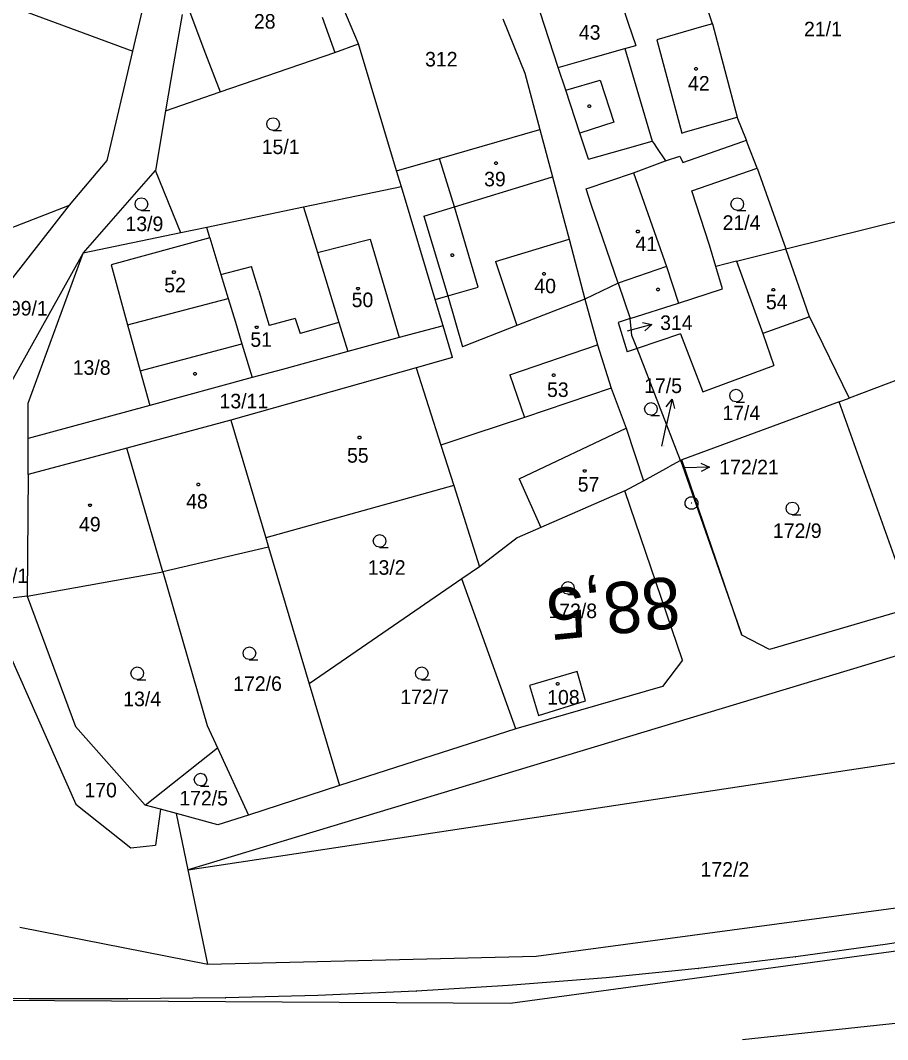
# Model space of a CAD drawing. Extents: x -780000 to -777378, y -1011169 to -1009297.
# Drawn here: x -779187.7 to -779086.3, y -1010479.3 to -1010360.1 of the extents above; entities that cross this region are included whole.
import ezdxf

# ---------------------------------------------------------------- set-up
doc = ezdxf.new("R2010")
doc.units = 0
for name, color, linetype in [('Default', 7, 'Continuous'), ('KN_HRANICE', 7, 'Continuous'), ('KN_KULTURY', 7, 'Continuous'), ('KN_PARCELY', 7, 'Continuous'), ('KN_SLUCKY', 7, 'Continuous'), ('KN_VEDENI', 7, 'Continuous'), ('Vrstva 7', 7, 'Continuous'), ('Železniční svršek', 7, 'Continuous')]:
    doc.layers.add(name, color=color, linetype=linetype)

# ---------------------------------------------------------------- blocks, each defined once
blk = doc.blocks.new('101')
at = {"layer": 'Default'}
blk.add_line((-0.05, 0), (0.05, 0), dxfattribs=at)
blk.add_lwpolyline([(0.19, 0.72), (0.53, 0.53), (0.72, 0.19), (0.72, -0.2), (0.53, -0.54), (0.19, -0.73), (-0.2, -0.73), (-0.54, -0.54), (-0.73, -0.2), (-0.73, 0.19), (-0.54, 0.53), (-0.2, 0.72), (0.19, 0.72)], dxfattribs=at)
blk = doc.blocks.new('304')
at = {"layer": 'Default'}
blk.add_lwpolyline([(0, 0), (-0.38, 0.1), (-0.65, 0.37), (-0.75, 0.74), (-0.65, 1.11), (-0.38, 1.38), (-0.01, 1.48), (0.36, 1.38), (0.63, 1.11), (0.73, 0.73), (0.63, 0.35), (0.36, 0.08), (-0.02, -0.02), (0.98, -0.02)], dxfattribs=at)
blk = doc.blocks.new('NAHRADNI_SYMBOL')
at = {"layer": 'Default'}
blk.add_lwpolyline([(0.09, 0.15), (0.18, 0), (0.09, -0.15), (-0.09, -0.15), (-0.18, 0), (-0.09, 0.15), (0.09, 0.15)], dxfattribs=at)
blk = doc.blocks.new('10292')
at = {"layer": 'Default'}
blk.add_line((0, 3), (0, 0), dxfattribs=at)
blk.add_lwpolyline([(-0.5, 2), (0, 3), (0.5, 2)], dxfattribs=at)
blk = doc.blocks.new('402')
at = {"layer": 'Default'}
blk.add_lwpolyline([(0.09, 0.15), (0.18, 0), (0.09, -0.15), (-0.09, -0.15), (-0.18, 0), (-0.09, 0.15), (0.09, 0.15)], dxfattribs=at)

msp = doc.modelspace()

# ---------------------------------------------------------------- linework, layer by layer
at = {"layer": 'KN_HRANICE'}
for p, q in [((-779174.51, -1010363.75), (-779172.96, -1010357.18)), ((-779106.8, -1010360.53), (-779107.71, -1010357.68)), ((-779187.61, -1010358.93), (-779174.51, -1010363.75)), ((-779148.14, -1010362.87), (-779149.85, -1010358.82)), ((-779124.81, -1010365.65), (-779126.93, -1010359.19)), ((-779117.35, -1010358.34), (-779116.64, -1010360.46)), ((-779168.77, -1010359.47), (-779169.76, -1010365.24)), ((-779131.3, -1010359.95), (-779128.72, -1010366.32)), ((-779116.64, -1010360.46), (-779115.76, -1010363.08)), ((-779106.8, -1010360.53), (-779103.91, -1010371.45)), ((-779150.92, -1010363.88), (-779148.14, -1010362.87)), ((-779143.7, -1010377.71), (-779148.14, -1010362.87)), ((-779177.51, -1010376.54), (-779174.51, -1010363.75)), ((-779164.31, -1010368.5), (-779150.92, -1010363.88)), ((-779117.03, -1010363.44), (-779115.76, -1010363.08)), ((-779117.03, -1010363.44), (-779113.83, -1010374.27)), ((-779169.76, -1010365.24), (-779170.69, -1010370.7)), ((-779128.72, -1010366.32), (-779126.96, -1010372.9)), ((-779123.93, -1010368.31), (-779124.81, -1010365.65)), ((-779170.69, -1010370.7), (-779164.31, -1010368.5)), ((-779122.28, -1010373.34), (-779123.93, -1010368.31)), ((-779170.69, -1010370.7), (-779171.88, -1010377.7)), ((-779102.81, -1010374.14), (-779103.91, -1010371.45)), ((-779138.68, -1010376.27), (-779126.96, -1010372.9)), ((-779126.96, -1010372.9), (-779125.49, -1010378.42)), ((-779121.28, -1010376.38), (-779122.28, -1010373.34)), ((-779117.26, -1010375.24), (-779113.83, -1010374.27)), ((-779102.69, -1010374.53), (-779102.81, -1010374.14)), ((-779101.55, -1010377.4), (-779102.69, -1010374.53)), ((-779121.28, -1010376.38), (-779117.26, -1010375.24)), ((-779181.94, -1010381.76), (-779177.51, -1010376.54)), ((-779143.7, -1010377.71), (-779138.68, -1010376.27)), ((-779116, -1010377.97), (-779112.28, -1010376.55)), ((-779180.32, -1010387.37), (-779171.88, -1010377.7)), ((-779168.93, -1010384.98), (-779171.88, -1010377.7)), ((-779143.14, -1010379.58), (-779143.7, -1010377.71)), ((-779134.12, -1010381.07), (-779125.49, -1010378.42)), ((-779125.49, -1010378.42), (-779124.04, -1010383.84)), ((-779121.56, -1010379.84), (-779116, -1010377.97)), ((-779109.18, -1010380.08), (-779101.55, -1010377.4)), ((-779101.55, -1010377.4), (-779098.22, -1010386.86)), ((-779143.14, -1010379.58), (-779154.57, -1010381.98)), ((-779139.2, -1010392.75), (-779143.14, -1010379.58)), ((-779120.97, -1010381.67), (-779121.56, -1010379.84)), ((-779107.15, -1010386.41), (-779109.18, -1010380.08)), ((-779098.22, -1010386.86), (-779071.95, -1010380.31)), ((-779192.12, -1010385.68), (-779181.94, -1010381.76)), ((-779190.77, -1010393.08), (-779181.94, -1010381.76)), ((-779154.57, -1010381.98), (-779165.87, -1010384.34)), ((-779154.57, -1010381.98), (-779152.95, -1010387.28)), ((-779140.53, -1010383.03), (-779136.94, -1010381.93)), ((-779136.94, -1010381.93), (-779134.12, -1010381.07)), ((-779117.8, -1010390.87), (-779120.97, -1010381.67)), ((-779140.53, -1010383.03), (-779137.7, -1010392.32)), ((-779165.87, -1010384.34), (-779168.93, -1010384.98)), ((-779165.53, -1010385.55), (-779165.87, -1010384.34)), ((-779124.04, -1010383.84), (-779123.54, -1010385.7)), ((-779168.93, -1010384.98), (-779180.32, -1010387.37)), ((-779165.53, -1010385.55), (-779177.07, -1010388.7)), ((-779165.53, -1010385.55), (-779164.23, -1010389.85)), ((-779123.54, -1010385.7), (-779121.71, -1010392.72)), ((-779106.38, -1010388.93), (-779107.15, -1010386.41)), ((-779103.99, -1010388.3), (-779098.22, -1010386.86)), ((-779095.45, -1010394.78), (-779098.22, -1010386.86)), ((-779190.91, -1010406.29), (-779180.32, -1010387.37)), ((-779186.74, -1010404.87), (-779180.32, -1010387.37)), ((-779152.95, -1010387.28), (-779150.45, -1010395.45)), ((-779177.07, -1010388.7), (-779175.14, -1010395.73)), ((-779103.99, -1010388.3), (-779106.38, -1010388.93)), ((-779105.6, -1010391.53), (-779106.38, -1010388.93)), ((-779164.23, -1010389.85), (-779163.38, -1010392.66)), ((-779117.8, -1010390.87), (-779121.71, -1010392.72)), ((-779117.8, -1010390.87), (-779116.39, -1010395)), ((-779110.74, -1010393.18), (-779105.6, -1010391.53)), ((-779163.38, -1010392.66), (-779162.54, -1010395.42)), ((-779139.2, -1010392.75), (-779137.7, -1010392.32)), ((-779138.27, -1010395.83), (-779139.2, -1010392.75)), ((-779137.7, -1010392.32), (-779136.01, -1010398.29)), ((-779121.71, -1010392.72), (-779129.66, -1010395.82)), ((-779121.71, -1010392.72), (-779120.21, -1010398.06)), ((-779116.39, -1010395), (-779110.74, -1010393.18)), ((-779116.39, -1010395), (-779117.81, -1010395.46)), ((-779116.19, -1010396.96), (-779116.39, -1010395)), ((-779095.45, -1010394.78), (-779100.91, -1010396.73)), ((-779095.45, -1010394.78), (-779090.81, -1010404.3)), ((-779175.14, -1010395.73), (-779173.66, -1010401.1)), ((-779162.54, -1010395.42), (-779161.78, -1010397.93)), ((-779150.45, -1010395.45), (-779149.41, -1010398.86)), ((-779138.27, -1010395.83), (-779143.38, -1010397.22)), ((-779137.16, -1010399.54), (-779138.27, -1010395.83)), ((-779129.66, -1010395.82), (-779136.01, -1010398.29)), ((-779117.81, -1010395.46), (-779116.75, -1010398.9)), ((-779143.38, -1010397.22), (-779149.41, -1010398.86)), ((-779115.59, -1010398.51), (-779116.19, -1010396.96)), ((-779110.51, -1010396.79), (-779115.59, -1010398.51)), ((-779110.51, -1010396.79), (-779107.93, -1010403.57)), ((-779100.91, -1010396.73), (-779099.61, -1010400.48)), ((-779161.78, -1010397.93), (-779160.58, -1010401.9)), ((-779120.21, -1010398.06), (-779118.64, -1010403.14)), ((-779115.59, -1010398.51), (-779116.75, -1010398.9)), ((-779110.52, -1010411.6), (-779115.59, -1010398.51)), ((-779149.41, -1010398.86), (-779157.03, -1010400.93)), ((-779137.16, -1010399.54), (-779141.41, -1010400.75)), ((-779173.66, -1010401.1), (-779172.54, -1010405.15)), ((-779141.41, -1010400.75), (-779163.08, -1010406.87)), ((-779157.03, -1010400.93), (-779160.58, -1010401.9)), ((-779141.41, -1010400.75), (-779138.52, -1010409.8)), ((-779107.93, -1010403.57), (-779099.61, -1010400.48)), ((-779080.88, -1010400.54), (-779090.81, -1010404.3)), ((-779160.58, -1010401.9), (-779172.54, -1010405.15)), ((-779118.64, -1010403.14), (-779128.76, -1010406.55)), ((-779118.64, -1010403.14), (-779116.88, -1010407.82)), ((-779091.99, -1010404.73), (-779110.38, -1010411.52)), ((-779091.99, -1010404.73), (-779090.81, -1010404.3)), ((-779083.42, -1010428.77), (-779091.99, -1010404.73)), ((-779186.75, -1010409.02), (-779186.74, -1010404.87)), ((-779172.54, -1010405.15), (-779186.75, -1010409.02)), ((-779163.08, -1010406.87), (-779175.21, -1010410.13)), ((-779163.08, -1010406.87), (-779158.98, -1010420.63)), ((-779128.76, -1010406.55), (-779134.68, -1010408.52)), ((-779116.88, -1010407.82), (-779114.86, -1010413.95)), ((-779186.75, -1010413.24), (-779186.75, -1010409.02)), ((-779134.68, -1010408.52), (-779138.52, -1010409.8)), ((-779175.21, -1010410.13), (-779186.75, -1010413.24)), ((-779171.02, -1010424.6), (-779175.21, -1010410.13)), ((-779138.52, -1010409.8), (-779137.02, -1010414.51)), ((-779110.52, -1010411.6), (-779111.87, -1010412.33)), ((-779110.52, -1010411.6), (-779110.38, -1010411.52)), ((-779110.52, -1010411.6), (-779110.28, -1010412.21)), ((-779103.35, -1010431.99), (-779110.38, -1010411.52)), ((-779114.86, -1010413.95), (-779111.87, -1010412.33)), ((-779110.28, -1010412.21), (-779103.35, -1010431.99)), ((-779186.75, -1010413.24), (-779186.88, -1010427.45)), ((-779117.03, -1010415.13), (-779114.86, -1010413.95)), ((-779137.02, -1010414.51), (-779158.98, -1010420.63)), ((-779137.02, -1010414.51), (-779134, -1010424)), ((-779117.03, -1010415.13), (-779126.85, -1010419.42)), ((-779110.3, -1010434.92), (-779117.03, -1010415.13)), ((-779126.85, -1010419.42), (-779129.59, -1010420.64)), ((-779158.98, -1010420.63), (-779158.66, -1010421.72)), ((-779129.59, -1010420.64), (-779134, -1010424)), ((-779158.66, -1010421.72), (-779171.02, -1010424.6)), ((-779158.66, -1010421.72), (-779153.92, -1010437.67)), ((-779186.88, -1010427.45), (-779171.02, -1010424.6)), ((-779171.02, -1010424.6), (-779165.83, -1010442.55)), ((-779134, -1010424), (-779136.09, -1010425.43)), ((-779136.09, -1010425.43), (-779153.92, -1010437.67)), ((-779129.76, -1010442.93), (-779136.09, -1010425.43)), ((-779186.88, -1010427.45), (-779195.06, -1010428.47)), ((-779186.88, -1010427.45), (-779181.22, -1010442.66)), ((-779063.54, -1010427.85), (-779168.06, -1010459.43)), ((-779083.42, -1010428.77), (-779100.12, -1010433.69)), ((-779190.11, -1010431.7), (-779181.17, -1010451.77)), ((-779100.12, -1010433.69), (-779103.35, -1010431.99)), ((-779110.3, -1010434.92), (-779112.61, -1010437.99)), ((-779122.59, -1010436.25), (-779128.15, -1010437.89)), ((-779121.63, -1010439.67), (-779122.59, -1010436.25)), ((-779153.92, -1010437.67), (-779150.37, -1010449.59)), ((-779112.61, -1010437.99), (-779129.76, -1010442.93)), ((-779128.15, -1010437.89), (-779127.13, -1010441.39)), ((-779127.13, -1010441.39), (-779121.63, -1010439.67)), ((-779181.22, -1010442.66), (-779173.08, -1010451.87)), ((-779165.83, -1010442.55), (-779164.63, -1010445.15)), ((-779129.76, -1010442.93), (-779150.37, -1010449.59)), ((-779173.08, -1010451.87), (-779164.63, -1010445.15)), ((-779164.63, -1010445.15), (-779161.01, -1010453.02)), ((-779168.06, -1010459.43), (-779084.08, -1010446.73)), ((-779150.37, -1010449.59), (-779161.01, -1010453.02)), ((-779181.17, -1010451.77), (-779174.76, -1010456.86)), ((-779171.3, -1010452.35), (-779173.08, -1010451.87)), ((-779171.3, -1010452.35), (-779171.87, -1010456.53)), ((-779169.43, -1010452.86), (-779171.3, -1010452.35)), ((-779164.59, -1010454.17), (-779169.43, -1010452.86)), ((-779168.06, -1010459.43), (-779169.43, -1010452.86)), ((-779161.01, -1010453.02), (-779164.59, -1010454.17)), ((-779174.76, -1010456.86), (-779171.87, -1010456.53)), ((-779165.75, -1010470.45), (-779168.06, -1010459.43)), ((-779127.38, -1010469.51), (-779070.54, -1010461.9)), ((-779187.71, -1010466.11), (-779165.75, -1010470.45)), ((-779165.75, -1010470.45), (-779127.38, -1010469.51)), ((-779103.26, -1010479.27), (-779067.56, -1010475.45))]:
    msp.add_line(p, q, dxfattribs=at)
for points in [[(-779113.83, -1010374.27), (-779113.61, -1010374.59), (-779113.33, -1010375), (-779112.28, -1010376.55)], [(-779112.28, -1010376.55), (-779110.58, -1010376.03), (-779110.25, -1010376.75), (-779103.23, -1010374.29), (-779102.81, -1010374.14)]]:
    msp.add_lwpolyline(points, dxfattribs=at)
at = {"layer": 'KN_PARCELY'}
msp.add_line((-779112.71, -1010409.91), (-779112.14, -1010407.36), dxfattribs=at)
at = {"layer": 'KN_SLUCKY'}
for p, q in [((-779167.87, -1010359.19), (-779166.01, -1010364.05)), ((-779152.41, -1010359.76), (-779150.92, -1010363.88)), ((-779166.01, -1010364.05), (-779164.31, -1010368.5)), ((-779120.72, -1010364.49), (-779117.03, -1010363.44)), ((-779124.81, -1010365.65), (-779120.72, -1010364.49)), ((-779123.93, -1010368.31), (-779119.9, -1010367.12)), ((-779119.9, -1010367.12), (-779118.3, -1010372.03)), ((-779118.3, -1010372.03), (-779122.28, -1010373.34)), ((-779136.94, -1010381.93), (-779138.68, -1010376.27)), ((-779116, -1010377.97), (-779112.15, -1010388.92)), ((-779134.17, -1010391.31), (-779136.94, -1010381.93)), ((-779152.95, -1010387.28), (-779146.78, -1010385.72)), ((-779146.78, -1010385.72), (-779143.38, -1010397.22)), ((-779132.14, -1010388.34), (-779123.54, -1010385.7)), ((-779164.23, -1010389.85), (-779160.66, -1010388.9)), ((-779159.81, -1010391.73), (-779160.66, -1010388.9)), ((-779132.14, -1010388.34), (-779129.66, -1010395.82)), ((-779112.15, -1010388.92), (-779117.8, -1010390.87)), ((-779112.15, -1010388.92), (-779110.74, -1010393.18)), ((-779103.99, -1010388.3), (-779100.91, -1010396.73)), ((-779137.7, -1010392.32), (-779134.17, -1010391.31)), ((-779175.14, -1010395.73), (-779163.38, -1010392.66)), ((-779159.81, -1010391.73), (-779159.01, -1010394.4)), ((-779159.01, -1010394.4), (-779158.58, -1010395.81)), ((-779155.55, -1010395), (-779158.58, -1010395.81)), ((-779155.55, -1010395), (-779154.97, -1010396.76)), ((-779150.45, -1010395.45), (-779154.97, -1010396.76)), ((-779173.66, -1010401.1), (-779161.78, -1010397.93)), ((-779130.48, -1010401.56), (-779120.21, -1010398.06)), ((-779130.48, -1010401.56), (-779128.76, -1010406.55)), ((-779129.37, -1010413.73), (-779116.88, -1010407.82)), ((-779129.37, -1010413.73), (-779126.85, -1010419.42))]:
    msp.add_line(p, q, dxfattribs=at)
msp.add_lwpolyline([(-779106.8, -1010360.53), (-779108.08, -1010360.89), (-779113.27, -1010362.41), (-779110.38, -1010373.33), (-779109.92, -1010373.16), (-779103.91, -1010371.45)], dxfattribs=at)
at = {"layer": 'KN_VEDENI'}
for p, q in [((-779130.44, -1010475.03), (-779042.85, -1010463.08)), ((-779395.56, -1010473.38), (-779130.44, -1010475.03))]:
    msp.add_line(p, q, dxfattribs=at)
at = {"layer": 'Železniční svršek'}
for points in [[(-779075.05, -1010466.31), (-779086.32, -1010468.1)], [(-779086.34, -1010468.1), (-779097.06, -1010469.6)], [(-779097.08, -1010469.6), (-779108.43, -1010470.97)], [(-779108.45, -1010470.97), (-779119.2, -1010472.04)], [(-779119.22, -1010472.04), (-779130.65, -1010472.94)], [(-779141.41, -1010473.61), (-779152.89, -1010474.1)], [(-779130.67, -1010472.95), (-779141.39, -1010473.61)], [(-779186.63, -1010474.52), (-779197.43, -1010474.45)], [(-779175.13, -1010474.5), (-779186.62, -1010474.52)], [(-779163.68, -1010474.37), (-779175.12, -1010474.5)], [(-779152.9, -1010474.1), (-779163.67, -1010474.37)]]:
    msp.add_lwpolyline(points, dxfattribs=at)
for centre, start, end in [((-779086.48, -1010467.11), 277.9522, 279.019), ((-779097.19, -1010468.61), 276.87, 277.9522), ((-779108.55, -1010469.97), 275.6827, 276.87), ((-779119.3, -1010471.04), 274.5242, 275.6827), ((-779141.45, -1010472.61), 272.4303, 273.5338), ((-779130.73, -1010471.95), 273.5338, 274.5242), ((-779186.62, -1010473.52), 269.6447, 270.0598), ((-779175.13, -1010473.5), 270.0598, 270.6655), ((-779163.69, -1010473.37), 270.6655, 271.461), ((-779152.93, -1010473.1), 271.461, 272.4303)]:
    msp.add_arc(centre, 1, start, end, dxfattribs=at)

# ---------------------------------------------------------------- block references
at = {"layer": 'KN_KULTURY'}
for name, p in [('402', (-779108.7, -1010365.82)), ('402', (-779121.17, -1010370.18)), ('304', (-779158.12, -1010373.01)), ('NAHRADNI_SYMBOL', (-779132.08, -1010376.83)), ('304', (-779173.5, -1010382.36)), ('304', (-779103.87, -1010382.35)), ('402', (-779115.51, -1010384.83)), ('402', (-779137.17, -1010387.58)), ('402', (-779169.73, -1010389.58)), ('402', (-779126.48, -1010389.76)), ('402', (-779148.2, -1010391.5)), ('402', (-779113.16, -1010391.61)), ('402', (-779099.68, -1010391.62)), ('402', (-779160.04, -1010396.02)), ('402', (-779167.26, -1010401.46)), ('402', (-779125.34, -1010401.62)), ('304', (-779104.01, -1010404.74)), ('304', (-779113.97, -1010406.29)), ('NAHRADNI_SYMBOL', (-779148.03, -1010408.91)), ('402', (-779121.72, -1010412.81)), ('NAHRADNI_SYMBOL', (-779166.87, -1010414.38)), ('304', (-779097.43, -1010417.92)), ('NAHRADNI_SYMBOL', (-779179.52, -1010416.82)), ('304', (-779145.67, -1010421.73)), ('304', (-779123.67, -1010427.22)), ('304', (-779160.89, -1010434.85)), ('304', (-779174, -1010437.19)), ('304', (-779140.75, -1010437.19)), ('402', (-779124.88, -1010437.7)), ('304', (-779166.6, -1010449.62))]:
    msp.add_blockref(name, p, dxfattribs=at)
at = {"layer": 'KN_PARCELY'}
for p, rotation in [((-779116.76, -1010396.47), -74.724314), ((-779112.14, -1010407.36), -12.501097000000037), ((-779110.13, -1010412.43), -88.76178)]:
    msp.add_blockref('10292', p, dxfattribs=dict(at, rotation=rotation))
msp.add_blockref('101', (-779109.23, -1010416.55), dxfattribs=at)

# ---------------------------------------------------------------- texts
for s, height, p in [('28', 1.7, (-779160.37, -1010361.11)), ('21/1', 1.7, (-779096.09, -1010362)), ('43', 1.7, (-779122.4, -1010362.4)), ('312', 1.7, (-779140.37, -1010365.53)), ('42', 1.7, (-779109.64, -1010368.35)), ('15/1', 1.7, (-779159.46, -1010375.77)), ('39', 1.7, (-779133.47, -1010379.54)), ('13/9', 1.7, (-779175.38, -1010384.77)), ('21/4', 1.7, (-779105.6, -1010384.63)), ('41', 1.7, (-779115.78, -1010387.11)), ('52', 1.7, (-779170.85, -1010391.93)), ('40', 1.7, (-779127.6, -1010392.04)), ('50', 1.7, (-779148.95, -1010393.66)), ('54', 1.7, (-779100.54, -1010393.91)), ('299/1', 1.7, (-779190.15, -1010394.64)), ('314', 1.7, (-779112.9, -1010396.33)), ('314', 0.1, (-779116.75, -1010396.47)), ('51', 1.7, (-779160.79, -1010398.3)), ('13/8', 1.7, (-779181.54, -1010401.57)), ('17/5', 1.7, (-779114.77, -1010403.7)), ('53', 1.7, (-779126.12, -1010404.16)), ('13/11', 1.7, (-779164.39, -1010405.49)), ('17/4', 1.7, (-779105.63, -1010406.87)), ('55', 1.7, (-779149.49, -1010411.84)), ('17/5', 0.1, (-779112.69, -1010409.91)), ('172/21', 1.7, (-779105.99, -1010413.2)), ('172/21', 0.1, (-779110.11, -1010412.43)), ('57', 1.7, (-779122.53, -1010415.22)), ('48', 1.7, (-779168.29, -1010417.2)), ('49', 1.7, (-779180.81, -1010419.88)), ('172/9', 1.7, (-779099.72, -1010420.64)), ('13/2', 1.7, (-779147.07, -1010424.94)), ('169/1', 1.7, (-779192.44, -1010425.91)), ('172/8', 1.7, (-779125.96, -1010430.01)), ('172/6', 1.7, (-779162.79, -1010438.51)), ('13/4', 1.7, (-779175.64, -1010440.3)), ('172/7', 1.7, (-779143.26, -1010440.06)), ('108', 1.7, (-779126.1, -1010440.11)), ('170', 1.7, (-779180.18, -1010450.96)), ('172/5', 1.7, (-779169.09, -1010451.9)), ('172/2', 1.7, (-779108.18, -1010460.23))]:
    msp.add_text(s, height=height, dxfattribs=at).set_placement(p)
at = {"layer": 'Vrstva 7'}
msp.add_text('88,5', height=6, rotation=185.6827, dxfattribs=at).set_placement((-779110.86, -1010425.11))

doc.saveas('drawing.dxf')
